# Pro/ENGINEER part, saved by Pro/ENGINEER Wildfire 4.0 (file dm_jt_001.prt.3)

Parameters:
  METRIC = "NO"

Other parameters: PITCH, DRILL_DIAMETER, THREAD_DIAMETER, THREADS_PER_INCH, THREAD_DEPTH, THREAD_LENGTH, DRILL_POINT_ANGLE, DRILL_DEPTH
